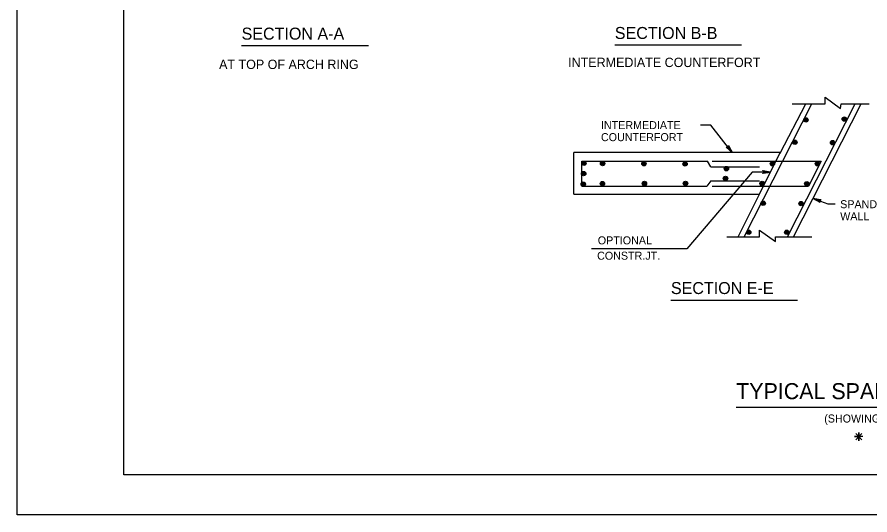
# Model space of a CAD drawing. Extents: x 639028 to 639883, y 298843 to 300031.
# Drawn here: x 639027.7 to 639347.3, y 298843.1 to 299029.7 of the extents above; entities that cross this region are included whole.
import ezdxf

# ---------------------------------------------------------------- set-up
doc = ezdxf.new("R2010")
doc.units = 0
for name, color, linetype in [('2', 7, 'Continuous'), ('52', 7, 'Continuous'), ('53', 7, 'Continuous'), ('PLT-BNDY', 7, 'Continuous')]:
    doc.layers.add(name, color=color, linetype=linetype)

msp = doc.modelspace()

# ---------------------------------------------------------------- linework, layer by layer
at = {"layer": '2'}
for p, q in [((639067.74, 298858.08), (639067.74, 299422.08)), ((639300.18, 298947.35), (639325.43, 298997.1)), ((639313.68, 298978.6), (639323.18, 298997.1)), ((639316.43, 298947.35), (639341.68, 298997.1)), ((639318.18, 298997.1), (639330.43, 298997.1)), ((639318.68, 298947.35), (639343.93, 298997.1)), ((639336.43, 298997.1), (639346.93, 298997.1)), ((639236.3, 298963.35), (639236.3, 298978.85)), ((639313.68, 298978.85), (639236.3, 298978.85)), ((639245.8, 298978.85), (639236.3, 298978.85)), ((639305.93, 298963.35), (639313.68, 298978.85)), ((639239.3, 298966.35), (639239.3, 298975.6)), ((639239.3, 298975.6), (639245.8, 298975.6)), ((639239.3, 298975.6), (639286.43, 298975.6)), ((639287.68, 298973.6), (639286.43, 298975.6)), ((639288.18, 298975.6), (639329.01, 298975.6)), ((639329.01, 298975.6), (639324.26, 298966.35)), ((639287.68, 298973.6), (639305.93, 298973.6)), ((639303.18, 298971.6), (639278.68, 298942.85)), ((639310.05, 298971.6), (639303.18, 298971.6)), ((639239.3, 298966.35), (639286.18, 298966.35)), ((639287.68, 298968.35), (639286.18, 298966.35)), ((639287.68, 298968.35), (639305.93, 298968.35)), ((639288.18, 298966.35), (639324.26, 298966.35)), ((639236.3, 298963.35), (639305.93, 298963.35)), ((639297.93, 298947.35), (639305.93, 298963.35)), ((639293.68, 298947.35), (639305.93, 298947.35)), ((639311.93, 298947.35), (639325.43, 298947.35)), ((639278.68, 298942.85), (639242.93, 298942.85)), ((639343.05, 298872.42), (639343.05, 298872.42)), ((639853.74, 298858.08), (639067.74, 298858.08))]:
    msp.add_line(p, q, dxfattribs=at)
for points in [[(639330.43, 298997.1), (639330.43, 298999.6), (639336.18, 298995.35), (639336.43, 298997.1)], [(639310.05, 298971.6), (639307.07, 298971.04), (639307.18, 298971.12), (639307.3, 298971.2), (639307.36, 298971.3), (639307.42, 298971.4), (639307.43, 298971.5), (639307.45, 298971.6), (639307.43, 298971.7), (639307.42, 298971.8), (639307.36, 298971.9), (639307.3, 298972), (639307.18, 298972.08), (639307.07, 298972.16), (639310.05, 298971.6), (639307.18, 298972.08), (639307.3, 298972), (639310.05, 298971.6), (639307.36, 298971.9), (639307.42, 298971.8), (639310.05, 298971.6), (639307.43, 298971.7), (639307.45, 298971.6), (639310.05, 298971.6), (639307.43, 298971.5), (639307.42, 298971.4), (639310.05, 298971.6), (639307.36, 298971.3), (639307.3, 298971.2), (639310.05, 298971.6), (639307.18, 298971.12)], [(639305.93, 298947.35), (639305.93, 298949.85), (639311.93, 298945.6), (639311.93, 298947.35)], [(639344.65, 298872.42), (639341.45, 298872.42), (639343.05, 298872.42), (639343.05, 298870.82), (639343.05, 298874.02), (639343.05, 298872.42), (639344.18, 298873.55), (639341.92, 298871.29), (639343.05, 298872.42), (639344.18, 298871.29), (639341.92, 298873.55)]]:
    msp.add_lwpolyline(points, dxfattribs=at)
for centre, radius in [((639323.26, 298991.1), 0.825), ((639323.26, 298991.09), 0.668), ((639323.26, 298991.09), 0.527), ((639323.26, 298991.07), 0.37), ((639337.67, 298991.43), 0.825), ((639337.67, 298991.42), 0.668), ((639337.67, 298991.42), 0.527), ((639337.67, 298991.4), 0.37), ((639337.67, 298991.43), 0.202), ((639337.68, 298991.42), 0.0569), ((639323.26, 298991.1), 0.202), ((639323.28, 298991.09), 0.0569), ((639319.11, 298982.75), 0.825), ((639319.12, 298982.74), 0.668), ((639319.12, 298982.74), 0.527), ((639319.12, 298982.72), 0.37), ((639319.12, 298982.75), 0.202), ((639319.13, 298982.74), 0.0569), ((639333.25, 298982.59), 0.825), ((639333.25, 298982.58), 0.668), ((639333.25, 298982.58), 0.527), ((639333.25, 298982.56), 0.37), ((639333.25, 298982.59), 0.202), ((639333.27, 298982.58), 0.0569), ((639240.1, 298974.88), 0.825), ((639240.1, 298974.87), 0.668), ((639247.1, 298974.78), 0.825), ((639247.1, 298974.77), 0.668), ((639262.58, 298974.73), 0.825), ((639278.01, 298974.63), 0.825), ((639310.71, 298974.73), 0.825), ((639327.58, 298974.73), 0.825), ((639240.1, 298974.87), 0.527), ((639240.1, 298974.85), 0.37), ((639240.1, 298974.88), 0.202), ((639240.12, 298974.87), 0.0569), ((639247.1, 298974.77), 0.527), ((639247.1, 298974.75), 0.37), ((639247.1, 298974.78), 0.202), ((639247.11, 298974.77), 0.0569), ((639262.58, 298974.72), 0.668), ((639262.58, 298974.72), 0.527), ((639262.58, 298974.7), 0.37), ((639262.58, 298974.73), 0.202), ((639262.6, 298974.72), 0.0569), ((639278.01, 298974.62), 0.668), ((639278.01, 298974.62), 0.527), ((639278.01, 298974.6), 0.37), ((639278.01, 298974.63), 0.202), ((639278.03, 298974.62), 0.0569), ((639293.49, 298972.85), 0.825), ((639293.49, 298972.84), 0.668), ((639293.49, 298972.84), 0.527), ((639293.49, 298972.83), 0.37), ((639293.49, 298972.86), 0.202), ((639293.51, 298972.84), 0.0569), ((639310.71, 298974.72), 0.668), ((639310.71, 298974.72), 0.527), ((639310.71, 298974.7), 0.37), ((639310.71, 298974.73), 0.202), ((639310.72, 298974.72), 0.0569), ((639327.58, 298974.72), 0.668), ((639327.58, 298974.72), 0.527), ((639327.58, 298974.7), 0.37), ((639327.58, 298974.73), 0.202), ((639327.6, 298974.72), 0.0569), ((639240, 298971.01), 0.825), ((639240, 298971), 0.668), ((639240, 298971), 0.527), ((639240, 298970.98), 0.37), ((639240, 298971.01), 0.202), ((639240.02, 298971), 0.0569), ((639293.15, 298969.2), 0.825), ((639293.15, 298969.19), 0.668), ((639293.15, 298969.19), 0.527), ((639293.15, 298969.18), 0.37), ((639293.15, 298969.2), 0.202), ((639293.16, 298969.19), 0.0569), ((639239.85, 298967.04), 0.825), ((639239.85, 298967.02), 0.668), ((639239.85, 298967.02), 0.527), ((639239.85, 298967.01), 0.37), ((639239.85, 298967.04), 0.202), ((639239.87, 298967.02), 0.0569), ((639247.05, 298967.24), 0.825), ((639247.05, 298967.23), 0.668), ((639247.05, 298967.23), 0.527), ((639247.05, 298967.21), 0.37), ((639247.05, 298967.24), 0.202), ((639247.06, 298967.23), 0.0569), ((639262.78, 298967.28), 0.825), ((639262.78, 298967.27), 0.668), ((639262.78, 298967.27), 0.527), ((639262.78, 298967.26), 0.37), ((639262.78, 298967.29), 0.202), ((639262.79, 298967.27), 0.0569), ((639278.16, 298967.34), 0.825), ((639278.16, 298967.32), 0.668), ((639278.16, 298967.32), 0.527), ((639278.16, 298967.31), 0.37), ((639278.16, 298967.34), 0.202), ((639278.18, 298967.32), 0.0569), ((639306.88, 298967.3), 0.825), ((639306.88, 298967.29), 0.668), ((639306.88, 298967.29), 0.527), ((639306.88, 298967.28), 0.37), ((639306.88, 298967.3), 0.202), ((639306.9, 298967.29), 0.0569), ((639323.6, 298967.19), 0.825), ((639323.6, 298967.18), 0.668), ((639323.6, 298967.18), 0.527), ((639323.6, 298967.17), 0.37), ((639323.6, 298967.19), 0.202), ((639323.61, 298967.18), 0.0569), ((639307.26, 298959.88), 0.825), ((639307.27, 298959.87), 0.668), ((639307.27, 298959.87), 0.527), ((639307.27, 298959.86), 0.37), ((639307.27, 298959.88), 0.202), ((639307.28, 298959.87), 0.0569), ((639321.46, 298959.77), 0.825), ((639321.46, 298959.76), 0.668), ((639321.46, 298959.76), 0.527), ((639321.46, 298959.75), 0.37), ((639321.46, 298959.77), 0.202), ((639321.47, 298959.76), 0.0569), ((639301.86, 298949.02), 0.825), ((639301.86, 298949.01), 0.668), ((639301.86, 298949.01), 0.527), ((639301.86, 298948.99), 0.37), ((639301.86, 298949.02), 0.202), ((639301.88, 298949.01), 0.0569), ((639316.11, 298949.02), 0.825), ((639316.11, 298949.01), 0.668), ((639316.11, 298949.01), 0.527), ((639316.11, 298948.99), 0.37), ((639316.11, 298949.02), 0.202), ((639316.12, 298949.01), 0.0569)]:
    msp.add_circle(centre, radius, dxfattribs=at)
at = {"layer": '52'}
for points in [[(639295.6, 298978.85), (639287.7, 298989.14), (639283.75, 298989.14)], [(639295.6, 298978.85), (639293.34, 298980.88), (639293.47, 298980.83), (639293.61, 298980.79), (639293.72, 298980.8), (639293.84, 298980.82), (639293.93, 298980.87), (639294.02, 298980.91), (639294.09, 298980.99), (639294.15, 298981.06), (639294.2, 298981.17), (639294.24, 298981.28), (639294.23, 298981.42), (639294.23, 298981.56), (639295.6, 298978.85), (639294.23, 298981.42), (639294.24, 298981.28), (639295.6, 298978.85), (639294.2, 298981.17), (639294.15, 298981.06), (639295.6, 298978.85), (639294.09, 298980.99), (639294.02, 298980.91), (639295.6, 298978.85), (639293.93, 298980.87), (639293.84, 298980.82), (639295.6, 298978.85), (639293.72, 298980.8), (639293.61, 298980.79), (639295.6, 298978.85), (639293.47, 298980.83)], [(639325.96, 298961.7), (639331.42, 298959.68), (639334.29, 298959.68)], [(639325.96, 298961.7), (639328.95, 298961.19), (639328.81, 298961.15), (639328.68, 298961.12), (639328.59, 298961.04), (639328.5, 298960.97), (639328.45, 298960.88), (639328.4, 298960.8), (639328.38, 298960.7), (639328.36, 298960.6), (639328.38, 298960.48), (639328.4, 298960.37), (639328.48, 298960.25), (639328.56, 298960.14), (639325.96, 298961.7), (639328.48, 298960.25), (639328.4, 298960.37), (639325.96, 298961.7), (639328.38, 298960.48), (639328.36, 298960.6), (639325.96, 298961.7), (639328.38, 298960.7), (639328.4, 298960.8), (639325.96, 298961.7), (639328.45, 298960.88), (639328.5, 298960.97), (639325.96, 298961.7), (639328.59, 298961.04), (639328.68, 298961.12), (639325.96, 298961.7), (639328.81, 298961.15)]]:
    msp.add_lwpolyline(points, dxfattribs=at)
at = {"layer": '53'}
for p, q in [((639111.86, 299018.95), (639159.42, 299018.95)), ((639251.68, 299019.2), (639299.09, 299019.2)), ((639272.69, 298923.61), (639320.07, 298923.61)), ((639297.14, 298883.47), (639467.45, 298883.47))]:
    msp.add_line(p, q, dxfattribs=at)
at = {"layer": 'PLT-BNDY'}
msp.add_lwpolyline([(639027.74, 299437.08), (639868.74, 299437.08), (639868.74, 298843.08), (639027.74, 298843.08)], close=True, dxfattribs=at)

# ---------------------------------------------------------------- texts
at = {"layer": '2'}
for s, p in [('INTERMEDIATE', (639246.49, 298987.67)), ('COUNTERFORT', (639246.49, 298983.17)), ('SPANDREL', (639336.11, 298958.03)), ('WALL', (639336.11, 298953.53)), ('OPTIONAL', (639245.3, 298944.48)), ('CONSTR.JT.', (639245.05, 298938.73)), ('(SHOWING REINFORCEMENT BARS LAYOUT.)', (639330.14, 298877.72))]:
    msp.add_text(s, height=3, dxfattribs=at).set_placement(p)
at = {"layer": '53'}
for s, height, p in [('SECTION A-A', 4.5, (639111.86, 299021.2)), ('SECTION B-B', 4.5, (639251.68, 299021.45)), ('INTERMEDIATE COUNTERFORT', 3.5, (639234.2, 299010.93)), ('AT TOP OF ARCH RING', 3.5, (639103.43, 299010.19)), ('SECTION E-E', 4.5, (639272.69, 298925.86)), ('TYPICAL SPANDREL WALL DETAILS', 6, (639297.14, 298886.47))]:
    msp.add_text(s, height=height, dxfattribs=at).set_placement(p)

doc.saveas('drawing.dxf')
